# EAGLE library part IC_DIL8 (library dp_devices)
Universal 8pins IC
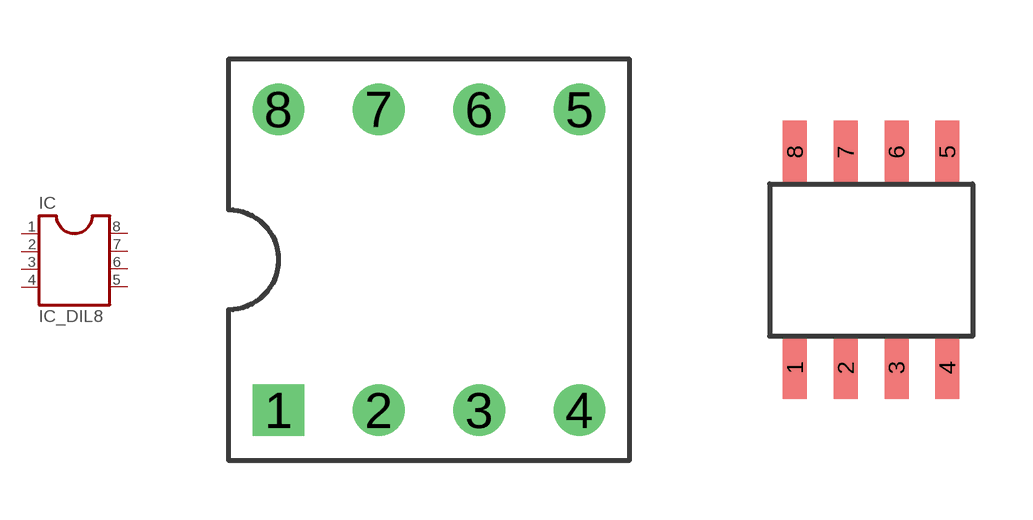
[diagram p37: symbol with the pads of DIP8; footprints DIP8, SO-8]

Designator prefix IC

## IC_DIL8-PTH  [DIP8]
1  1
2  2
3  3
4  4
5  5
6  6
7  7
8  8

## IC_DIL8-SO8  [SO-8]
Pads as for DIP8

## Footprint DIP8 (pad centres in mm)
drill 0.8 square: 1 -3.81,-3.81
drill 0.8 round: 2 -1.27,-3.81; 3 1.27,-3.81; 4 3.81,-3.81; 5 3.81,3.81; 6 1.27,3.81; 7 -1.27,3.81; 8 -3.81,3.81

## Footprint SO-8 (pad centres in mm)
smd 0.6 x 1.55: 1 -1.905,-2.69; 2 -0.635,-2.69; 3 0.635,-2.69; 4 1.905,-2.69; 5 1.905,2.71; 6 0.635,2.71; 7 -0.635,2.71; 8 -1.905,2.71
